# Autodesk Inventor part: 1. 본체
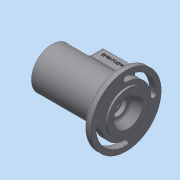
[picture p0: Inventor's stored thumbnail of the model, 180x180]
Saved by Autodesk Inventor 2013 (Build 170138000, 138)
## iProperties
Created: 2017-05
Part Number: 1. 본체
Material: 일반
Document SubType Name: Modeling
Designer: dgall
Density: 1 g/cm^3
Author: dgall
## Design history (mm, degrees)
sketch "스케치1"
  geometry: L1 (-57.5, 0)-(57.5, 0); L2 (-57.5, 31)-(44.5, 31); L3 (44.5, 31)-(44.5, 53); L4 (44.5, 53)-(54.5, 53); L5 (54.5, 53)-(54.5, 31); L6 (54.5, 31)-(57.5, 31); L7 (57.5, 31)-(57.5, 22); L8 (57.5, 22)-(43.5, 16); L9 (43.5, 16)-(43.5, 12.5); L10 (43.5, 12.5)-(36.2, 12.5); L11 (36.2, 12.5)-(36.2, 10); L12 (36.2, 10)-(33.5, 10); L13 (33.5, 10)-(33.5, 16.5); L14 (33.5, 16.5)-(28.5, 16.5); L15 (28.5, 16.5)-(28.5, 17.5); L16 (28.5, 17.5)-(17.5, 17.5); L17 (17.5, 17.5)-(17.5, 26); L18 (17.5, 26)-(-20.5, 26); L19 (-20.5, 26)-(-20.5, 17.5); L20 (-20.5, 17.5)-(-31.5, 17.5); L21 (-31.5, 17.5)-(-31.5, 18.5); L22 (-31.5, 18.5)-(-33.25, 18.5); L23 (-33.25, 18.5)-(-33.25, 17.5); L24 (-33.25, 17.5)-(-36.5, 17.5); L25 (-36.5, 17.5)-(-36.5, 20); L26 (-36.5, 20)-(-45.5, 20); L27 (-45.5, 20)-(-45.5, 24); L28 (-45.5, 24)-(-48.5, 24); L29 (-48.5, 24)-(-48.5, 21); L30 (-48.5, 21)-(-57.5, 21); L31 (-57.5, 31)-(-57.5, 21); 2 further points
  constraints: 62 end point, 12 parallel, 9 vertical alignment, 1 coincident, 1 collinear, 1 horizontal, 1 horizontal alignment, 1 midpoint, 1 perpendicular, 1 vertical
  dimensions: "d0" = 115 distance of L1.start L1.end; "d2" = 106 diameter of L4 L1; "d3" = 62 diameter of L6 L1; "d4" = 3 distance of L5.end L6.end; "d5" = 13 distance between parallel lines of L3 L7; "d6" = 44 diameter of L7.end L1; "d8" = 14 horizontal distance of L7.end L8.end; "d9" = 32 diameter of L8.end L1; "d10" = 25 diameter of L10 L1; "d11" = 20 diameter of L12 L1; "d12" = 7.3 distance of L9.end L10.end; "d13" = 2.7 distance of L11.end L12.end; "d14" = 33 diameter of L14 L1; "d15" = 35 diameter of L16 L1; "d16" = 42 diameter of L30 L1; "d17" = 48 diameter of L28 L1; "d18" = 40 diameter of L26 L1; "d19" = 35 diameter of L24 L1; "d20" = 37 diameter of L22 L1; "d21" = 35 diameter of L20 L1; "d22" = 52 diameter of L18 L1; "d23" = 3 distance of L27.end L28.end; "d24" = 12 distance between parallel lines of L27 L31; "d25" = 21 distance between parallel lines of L25 L31; "d27" = 38 distance of L17.end L18.end; "d29" = 10 distance between parallel lines of L9 L13; "d30" = 11 distance of L19.end L20.end; "d31" = 1.75 distance of L21.end L22.end; "d34" = 26 distance between parallel lines of L21 L31; "d35" = 60 distance between parallel lines of L21 L15
revolve "회전1" sketch "스케치1" stored, may be unused: angle "d36" = 90 deg
feature "스레드1" dims "d37" = 10, "d38" = 0
chamfer "모따기1" distance "d39" = 1; stored, may be unused: second distance "d40" = 2, angle "d41" = 45 deg
chamfer "모따기2" distance "d42" = 0.7; stored, may be unused: second distance "d43" = 2, angle "d44" = 30 deg
fillet "모깎기1" dims "d45" = 3
fillet "모깎기2" dims "d46" = 3
chamfer "모따기3" distance "d47" = 1; stored, may be unused: second distance "d48" = 2, angle "d49" = 30 deg
node "작업 평면1"
sketch "스케치2"
  geometry: L1 (26.5, -20)-(-23.5, -20); L2 (-23.5, -20)-(-23.5, 20); L3 (-23.5, 20)-(26.5, 20); L4 (26.5, 20)-(26.5, -20); L5 (56.5, 21)-(56.5, -21) reference; L6 (-14.5, -11)-(17.5, -11); L7 (17.5, -11)-(17.5, 11); L8 (17.5, 11)-(-14.5, 11); L9 (-14.5, 11)-(-14.5, -11); L10 (57.5, 31)-(57.5, -31) reference; 3 further points
  constraints: 16 end point, 4 parallel, 2 midpoint, 2 perpendicular, 1 horizontal, 1 horizontal alignment, 3 other
  dimensions: "d51" = 40 distance of L3.end L1.start; "d53" = 50 distance of L1.start L1.end; "d55" = 32 distance of L6.start L6.end; "d103" = 56 distance from line of L10 point (1.5, -20)
extrude "돌출1" join sketch "스케치2" stored distance "d56" = 10; taper "d57" = 0 deg
fillet "모깎기3" dims "d58" = 3
fillet "모깎기4" dims "d59" = 3
fillet "모깎기5" dims "d60" = 3
sketch "스케치3"
  geometry: L1 (-17.5, -8)-(-17.5, 8) reference; L2 (-14.5, 11)-(11.5, 11) reference; L3 (14.5, 8)-(14.5, -8) reference; L4 (11.5, -11)-(-14.5, -11) reference; A1 r 3 centre (-14.5, 8) between (-14.5, 11) and (-17.5, 8) reference; A2 r 3 centre (11.5, 8) between (14.5, 8) and (11.5, 11) reference; A3 r 3 centre (11.5, -8) between (11.5, -11) and (14.5, -8) reference; A4 r 3 centre (-14.5, -8) between (-17.5, -8) and (-14.5, -11) reference; 1 further point
extrude "돌출2" cut sketch "스케치3" stored distance "d61" = 10; taper "d62" = 0 deg
chamfer "모따기4" distance "d63" = 1; stored, may be unused: second distance "d64" = 2, angle "d65" = 30 deg
fillet "모깎기6" dims "d66" = 0.3
fillet "모깎기7" dims "d67" = 0.3
fillet "모깎기8" dims "d68" = 3
chamfer "모따기5" distance "d69" = 1; stored, may be unused: second distance "d70" = 2, angle "d71" = 30 deg
sketch "스케치4"
  geometry: L1 (11.5, 12)-(-14.5, 12) reference; 7 further points
  constraints: 2 horizontal alignment, 2 midpoint, 1 coincident, 1 vertical alignment
  dimensions: "d72" = 31 distance of point (-22, -15.5) point (-22, 15.5); "d74" = 41 distance of point (19, 15.5) point (-22, 15.5); "d76" = 15.5 vertical distance of point (0, 0) point (-22, 15.5); "d77" = 15.5 vertical distance of point (0, 0) point (-22, -15.5); "d102" = 20.5 horizontal distance of point (-1.5, 12) point (-22, 15.5)
hole "구멍1" sketch "스케치4" at (-22, 15.5), (-22, -15.5), (19, -15.5), (19, 15.5) diameter "d78" = 2.459; stored, may be unused: countersink angle "d82" = 90 deg, drill point angle "d84" = 118 deg; dims "d79" = 6, "d80" = 4, "d81" = 2, "d83" = 8
sketch "스케치5"
  geometry: C1 r 31 at (0, 0) reference; C2 r 53 at (0, 0) reference; A1 r 41.5 centre (0, 0) between (-41.5, 0) and (0, 41.5); A2 r 4 centre (-41.5, 0) between (-45.5, 0) and (-37.5, 0); A3 r 4 centre (0, 41.5) between (0, 37.5) and (0, 45.5); A4 r 4 centre (41.5, 0) between (45.5, 0) and (37.5, 0); A5 r 4 centre (0, -41.5) between (0, -37.5) and (0, -45.5); A6 r 45.5 centre (0, 0) between (0, 45.5) and (-45.5, 0); A7 r 45.5 centre (0, 0) between (0, -45.5) and (45.5, 0); A8 r 37.5 centre (0, 0) between (0, 37.5) and (-37.5, 0); A9 r 37.5 centre (0, 0) between (0, -37.5) and (37.5, 0); 1 further point
  constraints: 20 point on circle, 9 centre point, 3 coincident, 2 horizontal alignment, 2 vertical alignment
  dimensions: "d85" = 83 diameter of A1; "d88" = 45.5 radius of A6; "d89" = 37.5 radius of A8; "d90" = 4 radius of A3; "d91" = 4 radius of A2; "d92" = 45.5 radius of A7; "d93" = 37.5 radius of A9; "d94" = 4 radius of A5; "d95" = 4 radius of A4
extrude "돌출3" cut sketch "스케치5" stored distance "d96" = 10; taper "d97" = 0 deg
sketch "스케치6"
  geometry: L1 (44, 0)-(0, 0) reference; L2 (-34, -75)-(-34, -13) reference; 2 further points
  constraints: 1 other
  dimensions: "d98" = 56 distance from line of point (22, -8) L2; "d99" = 8 distance from line of point (22, -8) L1
feature "엠보싱1" sketch "스케치6" dims "d0" = 115, "d2" = 106, "d3" = 62, "d4" = 3, "d5" = 13, "d6" = 44, "d8" = 14, "d9" = 32, "d10" = 25, "d11" = 20, "d12" = 7.3, "d13" = 2.7, "d14" = 33, "d15" = 35, "d16" = 42, "d17" = 48, "d18" = 40, "d19" = 35, "d20" = 37, "d21" = 35, "d22" = 52, "d23" = 3, "d24" = 12, "d25" = 21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
fillet "모깎기9" dims "d104" = 3
node "솔리드1"
other parameters: "d50" = 44, "d86" = 91, "d87" = 75
